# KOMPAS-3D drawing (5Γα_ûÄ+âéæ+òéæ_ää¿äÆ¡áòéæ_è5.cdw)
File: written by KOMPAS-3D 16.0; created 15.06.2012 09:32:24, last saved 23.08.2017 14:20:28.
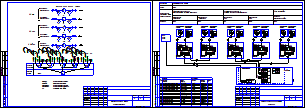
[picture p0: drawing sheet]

Sheets 1-2: A3, landscape

Title block, sheet 1: name: г. Москва, ул. Нежинская, д. 14, к.8 (кв. 1 и кв. 2); sheet number: 1; sheets: 27 / 28; sheet format: A3; stored path: D:\Проекты\Лыткарино\ул. Квартал 3А, д.25\710.74 РП.cdw; cell 320: Р
Title block, sheet 2: sheet number: 2

Views: Вид 2, Вид 3, Вид 4, Вид 5
Referenced files in C:\Program Files (x86)\ASCON\KOMPAS-3D V16\Sys\: SPDS.lcs, EngSys.lcs, GRAPHIC.LHS
Referenced files: graphic.tdp
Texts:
  МО, Клинский район, д. Решетниково, ул. Центральная, д.14
  GOST Common
  Normal
  List Paragraph
  heading 3
  для схемы
  txt
  краны
  Фоновая заливка
  Т0-элементы
  Преобразователь расхода
  Термопреобразователь
  Преобразователь давления
  Преобразователь цифровой
  Системный блок МКТС
  Агрегат
  Системный блок  МКТС
  Среда
  Вода
  параметра и место
  отбора импульса
  Учет тепловой энергии и
  теплоносителя системы отопления
  Подающий
  трубопровод
  отопления
  Обратный
  расхода горячей водысистемы ГВС
  Вводной
  трубопровод ХВС
  Узел учета ХВС
  ГВС
  ИМ1
  ИМ2
  ИМ3
  ИМ4
  ИМ5
  ВРУ
  приборы
  по месту
  шкаф
  учета
  UQIES
  Функциональная схема
  УУГВС
  УУТЭ
  УУХВС
  Pt 100
  Преобразователь
  температуры
  давления
  UP+
  UP-
  ИМП
  Лин
  Измерительный
  модуль М121
  Плата подключений
  СБ МКТС
  каб.
  Начало
  трассы
  Трассы
  Марка
  Проложен
  Датчик температуры (Т1)
  Датчик температуры (Т2)
  Датчик температуры (Т3)
  Датчик температуры (Т4)
  Датчик давления (Т1)
  Датчик температуры (В1)
  Датчик давления (Т2)
  Датчик давления (Т3)
  Датчик давления (В1)
  Датчик давления (Т4)
  Изм. модуль (Т1)
  Изм. модуль (Т2)
  Изм. модуль (Т3)
  Изм. модуль (Т4)
  Изм. модуль (В1)
  ВРУ 220В, 50 Гц
  ИМ1 УУТЭ
  ИМ2 УУТЭ
  ИМ1 УУГВС
  ИМ2 УУГВС
  ИМ1 УУХВС
  ИМ (Т1)
  ИМ (Т3)
  FTP
  ПВС
  Конец
  Кол-во и
  сеч. жил
  Длина,
  Размеры, параметризация
  сит. план
  подача ГВС
  обратка ГВС
  хвс
  обратка
  POLYLINE_STYLE_0.25_RGB_0_0_0
  стены
  Основная (не является границей для штриховки)
  POLYLINE_STYLE_0.18_RGB_0_0_0
  ХВС
  зеленая
  Красная тонкая
  арматура
  Подача
  Скрытая линия
  Ось Z
  Ось Y
  Ось X
  Образующая трубопровода (проектируемого)
  Трубопровод толщиной 0.6мм (одна линия)
  Трубопровод толщиной 1.2мм (одна линия)
  Трубопровод толщиной 1.0мм (одна линия)
  Трубопровод толщиной 0.8мм (одна линия)
  Трубопровод существующий (одна линия)
  Трубопровод невидимый (одна линия)
  Трубопровод демонтируемый (одна линия)
  Осевая трубопровода
  Осевая трубопровода (демонтируемого)
  Образующая трубопровода (существующего)
  Образующая трубопровода (невидимого)
  Изолированный трубопровод проектируемый (одна линия)
  Изолированный трубопровод существующий (одна линия)
  Образующая изоляции
  Изоляция
  Изолированный трубопровод невидимый (одна линия)
  Штрих пвс 075
  штрих пвс 2,5
  существующее оборудование
  Существующее оборудование
  K5LT_BASIC_RGB_0_0_255_THICK_0.53
  POLYLINE_STYLE_1.51_RGB_0_0_255
  POLYLINE_STYLE_0.50_RGB_128_128_128
  K5LT_AXLED_RGB_255_128_0_SC_1_THICK_0.18
  ACAD_ISO04W100_RGB_0_0_0_SC_1_THICK_0.18
  тонкая черная
  пломбировка
  Провода
  синий штрих
  Стили документа
  G2co
  расход вторичной воды объемный
  расход вторичной воды объемный при 70гр
  Gco
  расход теплоносителя массовый
  расход теплоносит объемн подающ
  расход теплоносит объемн обр
  Лапир
  Ghvs
  Im1
  Im2
  Im3
  Im4
  Im5
  Khvs
  норматив ХВС
  число подъездов
  число этажей
  Nkv
  число квартир
  тепловая нагрузка на отопление
  сумма Q
  Qgvs
  тепловая нагрузка ГВС
  тепловая нагрузка на циркуляцию ГВС
  иммитовставка или под манометр
  ro1
  ro2
  ro3
  ro4
  верх предел темп граф
  нижн предел темп граф
  темп подачи ГВС
  темп обр ГВС
  темр хол воды
  vzdh
  Kchn
  Ktp
  Knp
  beta
  tnv
  Vклап
  KLP
  RPD
  RDS
  PUMP
  ro5
  Переход К-76 x 3-38 x 2-09Г2С ГОСТ 17378-2001
  Переход ГОСТ 17378-2001
  Переход
  ГОСТ
  Сталь 09Г2С ГОСТ 19281-89
  Переход К-76 x 3-45 x 2,5-09Г2С ГОСТ 17378-2001
  Переход К-57 x 3-38 x 2-09Г2С ГОСТ 17378-2001
  Переход К-57 x 3-32 x 2-09Г2С ГОСТ 17378-2001
  Втулка 20x50
  Переход К-108 x 4-57 x 3-09Г2С ГОСТ 17378-2001
  Переход К-45 x 2,5-32 x 2-09Г2С ГОСТ 17378-2001
  Переход К-89 x 3,5-45 x 2,5-09Г2С ГОСТ 17378-2001
  Переход К-133 x 5-108 x 4-09Г2С ГОСТ 17378-2001
  Переход К-159 x 4,5-89 x 3,5-09Г2С ГОСТ 17378-2001
  Переход К-45 x 2,5-38 x 2-09Г2С ГОСТ 17378-2001
  Фланец 1-32-1 Ст3сп ГОСТ 12820-80
  Фланцы
  Фланец
  квадратный
  Ст3сп
  Ст3сп ГОСТ 380-2005
  Переход К-57 x 3-45 x 2,5-09Г2С ГОСТ 17378-2001
  Переход К-76 x 3-57 x 3-09Г2С ГОСТ 17378-2001
  Фланец 1-50-16 Ст3сп ГОСТ 12821-80
  Переход К-89 x 3,5-76 x 3,5-09Г2С ГОСТ 17378-2001
  Переход К-108 x 4-89 x 3,5-09Г2С ГОСТ 17378-2001
  Тройник 159 x 4,5-09Г2С ГОСТ 17376-2001
  Тройники ГОСТ 17376-2001
  Тройник
  Отвод 90-159 x 4-09Г2С ГОСТ 17375-2001
  Отвод ГОСТ 17375-2001
  Отвод
  Переход К-108 x 4-76 x 3,5-09Г2С ГОСТ 17378-2001
  Переход К-159 x 4,5-108 x 4-09Г2С ГОСТ 17378-2001
  Переход К-133 x 5-76 x 3,5-09Г2С ГОСТ 17378-2001
  Переход К-133 x 4-89 x 3,5-09Г2С ГОСТ 17378-2001
  Переход К-1-42,4 x 2,6-21,3 x 2-TS10 ГОСТ 17378-2001
  TS10
  Сталь TS10 ИСО 2604/2-75
  Фланец 1-20-16 Ст3сп ГОСТ 12820-80
  Лит-Масса-Масштаб
  Материал-Предприятие
  Title Specification
  Body Specification ( left align )
  Body Specificaton ( centered )
  Поз.
  Кол.
  Приме-
  чание
  Таблица спецификации
  Засыпка
  Штрих3
  Штрих2
  Штрих1
  Песок
  Штр0.5пр7
  Штр0.5пр12
  Штр0.3пр10
  Штр1.4пр21.21
  Штр1пр15
  Штр2.12пр35
  Штр1.5пр25
  Штр2.82пр42.42
  Штр2пр30
  SACNCR_ISO 1
  Электрощитовая
  Пр-1
  Ок-1
  вапвыапвы
  Обозначение стандарта
  Типоразмер
  Разраб.
  Пров.
  Т.контр.
  Н.контр.
  Утв.
  автоматизации
  Рабочие чертежи основного комплекта. ГОСТ Р 21.1101-2009 Ф3
  Стадия
  Лист
  Листов
  Изм.
  Кол.уч.
  №док.
  Подп.
  Дата
  Изменение
  Номер документа
  Подпись
  Наименование объекта строительства, в состав которого входит здание, наим. микр
  Наименование здания (сооружения)
  Порядковый номер листа
  Количество листов в документе
  Наименование изображения
  Индекс предприятия, выпускающего документ
  Инв. № подл.
  Подп. и дата
  Взам. инв. №
  Инвентарный номер подлинника
  Подпись принявшего подлинник на хранение
  Инвентарный номер подлинника, взамен которого выпущен данный подлинник
  Согласовано
  Формат листа
  Согласование
  03 Рабочие чертежи основного комплекта. ГОСТ Р 21.1101-2009 Ф3
  Схема соединений внешних
  проводок
Dimensions and other numbers on the sheet: 0; 21; 2; 4; 1,2,3,4,5; 6,7,8,9,10; 11,12,13,14,15; 16,17,18,19,20; 220В; 50Гц; 6; 5; 1; 3; 12; 16; 17; 11; 7; 18; 60; 4,0; 2,6582; 0,0160; 95; 2,6160; 3,0; 0,7862; 0,0060; 70; 9; 10; 13; 14; 8; 19; 15; 0,4088; 50; 20; 0,0; 0,0000; 4-20; 2x2x0,52; 3х0,75; 25; 09Г2С; 22; 23; 24; 26; 30; 31; 33; 34; 52; 64; 65; 66; 67; 69; 71; 72; 73; 74; 75; 27; 28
